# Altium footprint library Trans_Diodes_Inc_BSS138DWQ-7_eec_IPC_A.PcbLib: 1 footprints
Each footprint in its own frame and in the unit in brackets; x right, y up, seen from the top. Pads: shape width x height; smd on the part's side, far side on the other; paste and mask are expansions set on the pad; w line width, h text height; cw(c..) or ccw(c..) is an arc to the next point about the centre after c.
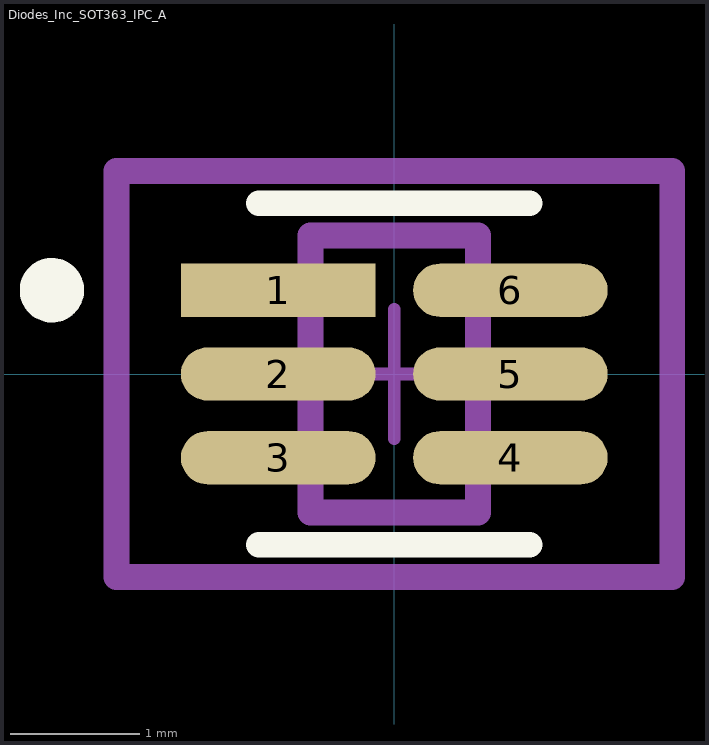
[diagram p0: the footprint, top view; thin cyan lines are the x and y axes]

## Diodes_Inc_SOT363_IPC_A [mm]
pads (6):
  rect 1.51x0.412 smd paste+0 mask+0: 1(-0.901,0.65)
  rrect100% 1.51x0.412 smd paste+0 mask+0: 2(-0.901,0) 3(-0.901,-0.65) 4(0.901,-0.65) 5(0.901,0) 6(0.901,0.65)
Top Overlay:
  circle w0.25: c-2.656,0.65 r0.125
  lines w0.2: -1.05,-1.325 1.05,-1.325 ; -1.05,1.325 1.05,1.325
Mechanical 10:
  lines w0.2: -2.156,-1.575 2.156,-1.575 2.156,1.575 -2.156,1.575 -2.156,-1.575
  text ".Designator" at 0,0.188 h1
Mechanical 12:
  lines w0.2: -0.65,-1.075 0.65,-1.075 0.65,1.075 -0.65,1.075 -0.65,-1.075
Mechanical 15:
  lines w0.1: -0.5,0 0.5,0 ; 0,-0.5 0,0.5
  lines w0.2: -2.156,-1.575 2.156,-1.575 2.156,1.575 -2.156,1.575 -2.156,-1.575
3D body "Trans_Diodes_Inc_BSS138DWQ-7_eec.STEP": height 0.25, standoff 0, extent -2.156,-1.575 2.156,1.575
